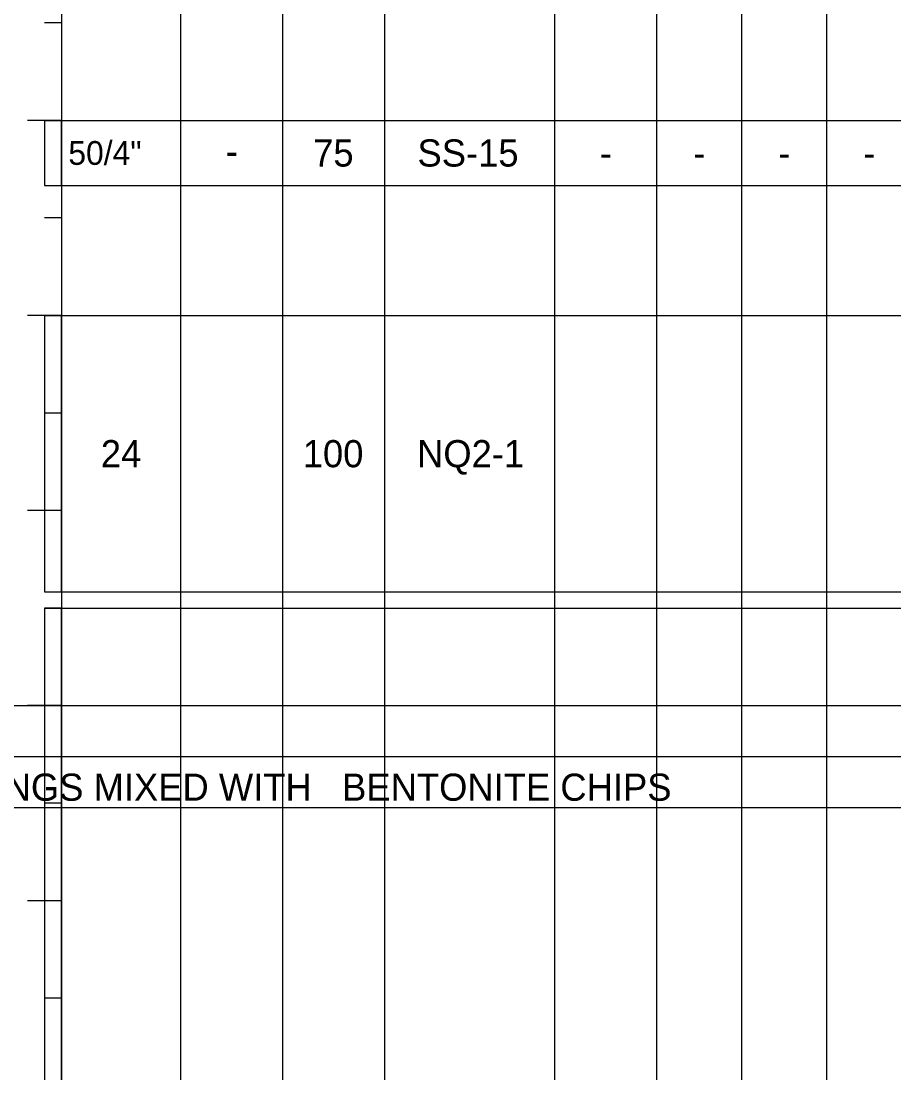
# Model space of a CAD drawing. Extents: x -0.01 to 0.83, y -0.63 to 1.27.
# Drawn here: x 0.4026 to 0.6165, y -0.0901 to 0.1679 of the extents above; entities that cross this region are included whole.
import ezdxf

# ---------------------------------------------------------------- set-up
doc = ezdxf.new("R2010")
doc.units = 0

msp = doc.modelspace()

# ---------------------------------------------------------------- linework, layer by layer
for points in [[(0, 0), (0.83333, 0), (0.83333, 1.275), (0, 1.275)], [(0, 0), (0.83333, 0), (0.83333, 1.275), (0, 1.275)], [(0, 0), (0.83333, 0), (0.83333, 1.275), (0, 1.275)], [(0, 0), (0.83333, 0), (0.83333, 1.275), (0, 1.275)], [(0, 0), (0.83333, 0), (0.83333, 1.275), (0, 1.275)], [(0.40833, 0.12756), (0.4125, 0.12756), (0.4125, 0.1435), (0.40833, 0.1435)], [(0.40833, 0.0279), (0.4125, 0.0279), (0.4125, 0.09567), (0.40833, 0.09567)], [(0.40833, -0.21525), (0.4125, -0.21525), (0.4125, 0.02392), (0.40833, 0.02392)]]:
    msp.add_lwpolyline(points, close=True)
for points in [[(0.4125, 1.22083), (0.4125, -0.62183)], [(0.4125, 1.22083), (0.4125, -0.62183)], [(0.44167, 1.22083), (0.44167, -0.62183)], [(0.46667, 1.22083), (0.46667, -0.62183)], [(0.49167, 1.22083), (0.49167, -0.62183)], [(0.53333, 1.22083), (0.53333, -0.62183)], [(0.55833, 1.22083), (0.55833, -0.62183)], [(0.57917, 1.20833), (0.57917, -0.62183)], [(0.6, 1.20833), (0.6, -0.62183)], [(0.4125, 0.16742), (0.40833, 0.16742)], [(0.4125, 0.1435), (0.40417, 0.1435)], [(0.40833, 0.1435), (0.40833, 0.12756)], [(0.40833, 0.1435), (0.4125, 0.1435)], [(0.4125, 0.1435), (0.40833, 0.1435)], [(0.4125, 0.1435), (0.44167, 0.1435)], [(0.44167, 0.1435), (0.46667, 0.1435)], [(0.46667, 0.1435), (0.49167, 0.1435)], [(0.49167, 0.1435), (0.53333, 0.1435)], [(0.53333, 0.1435), (0.55833, 0.1435)], [(0.55833, 0.1435), (0.57917, 0.1435)], [(0.57917, 0.1435), (0.6, 0.1435)], [(0.6, 0.1435), (0.62083, 0.1435)], [(0.40833, 0.12756), (0.4125, 0.12756)], [(0.4125, 0.12756), (0.44167, 0.12756)], [(0.44167, 0.12756), (0.46667, 0.12756)], [(0.46667, 0.12756), (0.49167, 0.12756)], [(0.49167, 0.12756), (0.53333, 0.12756)], [(0.53333, 0.12756), (0.55833, 0.12756)], [(0.55833, 0.12756), (0.57917, 0.12756)], [(0.57917, 0.12756), (0.6, 0.12756)], [(0.6, 0.12756), (0.62083, 0.12756)], [(0.4125, 0.11958), (0.40833, 0.11958)], [(0.4125, 0.09567), (0.40417, 0.09567)], [(0.40833, 0.09567), (0.40833, 0.0279)], [(0.40833, 0.09567), (0.4125, 0.09567)], [(0.4125, 0.09567), (0.40833, 0.09567)], [(0.4125, 0.09567), (0.44167, 0.09567)], [(0.44167, 0.09567), (0.46667, 0.09567)], [(0.46667, 0.09567), (0.49167, 0.09567)], [(0.49167, 0.09567), (0.53333, 0.09567)], [(0.53333, 0.09567), (0.55833, 0.09567)], [(0.55833, 0.09567), (0.57917, 0.09567)], [(0.57917, 0.09567), (0.6, 0.09567)], [(0.6, 0.09567), (0.62083, 0.09567)], [(0, 0.0875), (0, -0.025), (0.83333, -0.025), (0.83333, 0.0875)], [(0.4125, 0.07175), (0.40833, 0.07175)], [(0.4125, 0.04783), (0.40417, 0.04783)], [(0.4125, 0.04783), (0.40833, 0.04783)], [(0.40833, 0.0279), (0.4125, 0.0279)], [(0.4125, 0.0279), (0.44167, 0.0279)], [(0.44167, 0.0279), (0.46667, 0.0279)], [(0.46667, 0.0279), (0.49167, 0.0279)], [(0.49167, 0.0279), (0.53333, 0.0279)], [(0.53333, 0.0279), (0.55833, 0.0279)], [(0.55833, 0.0279), (0.57917, 0.0279)], [(0.57917, 0.0279), (0.6, 0.0279)], [(0.6, 0.0279), (0.62083, 0.0279)], [(0.40833, 0.02392), (0.40833, -0.21525)], [(0.40833, 0.02392), (0.4125, 0.02392)], [(0.4125, 0.02392), (0.40833, 0.02392)], [(0.4125, 0.02392), (0.44167, 0.02392)], [(0.44167, 0.02392), (0.46667, 0.02392)], [(0.46667, 0.02392), (0.49167, 0.02392)], [(0.49167, 0.02392), (0.53333, 0.02392)], [(0.53333, 0.02392), (0.55833, 0.02392)], [(0.55833, 0.02392), (0.57917, 0.02392)], [(0.57917, 0.02392), (0.6, 0.02392)], [(0.6, 0.02392), (0.62083, 0.02392)], [(0, 0), (0.83333, 0)], [(0.4125, 0), (0.40417, 0)], [(0.4125, 0), (0.40833, 0)], [(0, -0.0125), (0.83333, -0.0125)], [(0.4125, -0.02392), (0.40833, -0.02392)], [(0.4125, -0.04783), (0.40417, -0.04783)], [(0.4125, -0.04783), (0.40833, -0.04783)], [(0.4125, -0.07175), (0.40833, -0.07175)]]:
    msp.add_lwpolyline(points)

# ---------------------------------------------------------------- texts
for s, height, p in [('50/4"', 0.005833, (0.41417, 0.13261)), ('75', 0.006667, (0.47417, 0.13219)), ('SS-15', 0.006667, (0.49974, 0.13219)), ('-', 0.00667, (0.45276, 0.13261)), ('-', 0.00667, (0.54443, 0.13219)), ('-', 0.00667, (0.56734, 0.13219)), ('-', 0.00667, (0.58818, 0.13219)), ('-', 0.00667, (0.60901, 0.13219)), ('24', 0.006667, (0.42213, 0.05845)), ('100', 0.006667, (0.47162, 0.05845)), ('NQ2-1', 0.006667, (0.49964, 0.05845)), ('ASPHALT PATCH; AUGER CUTTINGS MIXED WITH   BENTONITE CHIPS', 0.0066667, (0.25986, -0.02333))]:
    msp.add_text(s, height=height).set_placement(p)

doc.saveas('drawing.dxf')
